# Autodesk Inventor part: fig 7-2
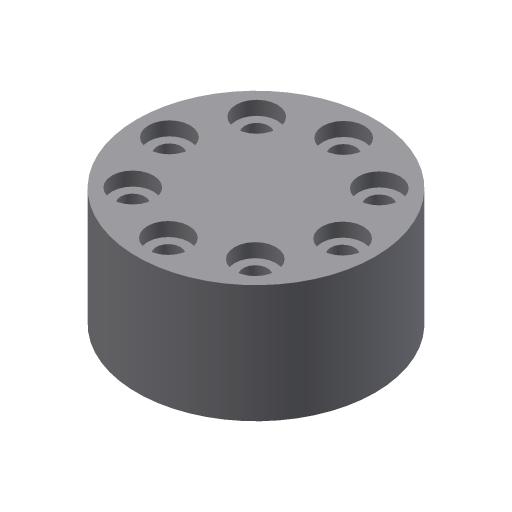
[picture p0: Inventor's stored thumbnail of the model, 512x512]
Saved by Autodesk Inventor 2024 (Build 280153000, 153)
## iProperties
Created: 2004-05
Part Number: fig 7-2
Document SubType Name: Modeling
Designer: CADCIM Technologies
Manufacturer: Standard
Standards Organization: Custom
Density: 1 g/cm^3
Material: Generic
Appearance: Default
Author: CADCIM Technologies
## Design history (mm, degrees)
sketch "Sketch1"
  geometry: C1 r 17.175 at (0, 0)
  constraints: 1 centre point
extrude "Extrusion1" new body sketch "Sketch1" distance "d0" = 17; taper "d1" = 0 deg
sketch "Sketch2"
  geometry: 1 further point
hole "Hole1" sketch "Sketch2" at (12.571, -0.074) diameter "d2" = 3.5; stored, may be unused: countersink angle "d6" = 90 deg, drill point angle "d8" = 118 deg; dims "d3" = 6, "d4" = 6, "d5" = 2, "d7" = 8
pattern_circular "Circular Pattern1" dims angle "d11" = 360 deg
body "Solid1"
